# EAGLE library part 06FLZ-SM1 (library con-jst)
CONNECTOR
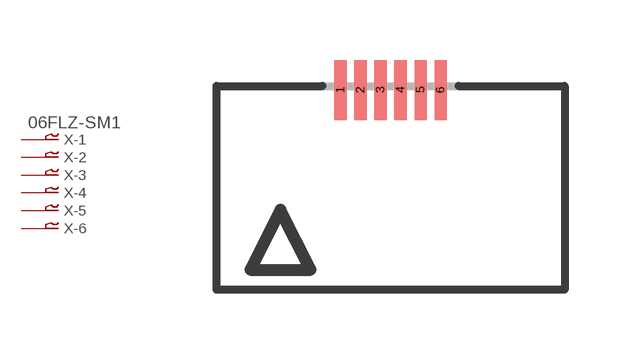
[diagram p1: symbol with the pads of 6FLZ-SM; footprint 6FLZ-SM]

Designator prefix X; gates -1=P-VN -2=P-N -3=P-N -4=P-N -5=P-N -6=P-N

## 06FLZ-SM1 (OC_FARNELL: unknown; OC_NEWARK: unknown)  [6FLZ-SM]
1  -1:1  pas
2  -2:1  pas
3  -3:1  pas
4  -4:1  pas
5  -5:1  pas
6  -6:1  pas

## Footprint 6FLZ-SM (pad centres in mm)
CONNECTOR
smd 0.3 x 1.5: 1 -1.25,2.5; 2 -0.75,2.5; 3 -0.25,2.5; 4 0.25,2.5; 5 0.75,2.5; 6 1.25,2.5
